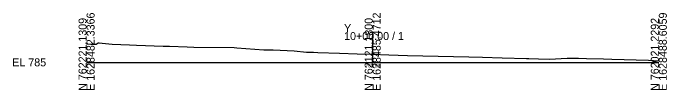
# Model space of a CAD drawing. Extents: x -26 to 203, y -10 to 4017.
# Drawn here: x -25.7 to 202.8, y -9.7 to 17.3 of the extents above; entities that cross this region are included whole.
import ezdxf

# ---------------------------------------------------------------- set-up
doc = ezdxf.new("R2010")
doc.units = 0
for name, color, linetype in [('Default', 7, 'Continuous'), ('Exist Cross Section Cell', 7, 'Continuous'), ('Exist XS Center Line Elevation Label', 7, 'Continuous'), ('Exist XS Ground Line', 7, 'Continuous')]:
    doc.layers.add(name, color=color, linetype=linetype)

msp = doc.modelspace()

# ---------------------------------------------------------------- linework, layer by layer
at = {"layer": 'Exist Cross Section Cell'}
for p, q in [((100, 0), (100, 10.64)), ((0, 0), (100, 0)), ((100, 0), (200, 0))]:
    msp.add_line(p, q, dxfattribs=at)
at = {"layer": 'Exist XS Ground Line'}
msp.add_lwpolyline([(0, 6.52), (1.54, 6.44), (2.84, 6.39), (3.34, 6.37), (4.04, 6.84), (4.35, 6.83), (5.41, 6.76), (8.91, 6.43), (14.99, 6.19), (17.48, 6.09), (26.79, 5.71), (28.97, 5.74), (35.14, 5.41), (37.52, 5.39), (51.57, 5.21), (52.53, 5.14), (61.93, 4.45), (65.22, 4.36), (72.6, 4.09), (76.91, 3.6), (77.76, 3.54), (79.34, 3.57), (80.79, 3.42), (88.36, 3.19), (94.59, 3), (99.75, 2.84), (105.59, 2.61), (112.15, 2.42), (133.56, 1.99), (138.39, 1.83), (145.29, 1.59), (153.77, 1.34), (154.52, 1.32), (158, 1.26), (161.81, 1.17), (167.93, 1.53), (168.51, 1.53), (169.81, 1.5), (171.99, 1.46), (174.74, 1.41), (180.72, 1.26), (183.53, 1.17), (196.43, 0.78), (200, 0.59)], dxfattribs=at)

# ---------------------------------------------------------------- texts
at = {"layer": 'Default'}
msp.add_text('-', height=0.0001, dxfattribs=at).set_placement((0, 0))
at = {"layer": 'Exist Cross Section Cell'}
for s, p in [('E 1628482.3366', (2.8, -10)), ('E 1628485.4712', (102.8, -10)), ('E 1628488.6059', (202.8, -10)), ('N 762221.1309', (0, -10)), ('N 762121.1800', (100, -10)), ('N 762021.2292', (200, -10))]:
    msp.add_text(s, height=2.8, rotation=90, dxfattribs=at).set_placement(p)
for s, p in [('Y', (90, 10.64)), ('10+00.00 / 1', (90, 7.84)), ('EL 785', (-26, -1.4))]:
    msp.add_text(s, height=2.8, dxfattribs=at).set_placement(p)
at = {"layer": 'Exist XS Center Line Elevation Label'}
msp.add_text('787.83', height=1.2, dxfattribs=at).set_placement((97.46, -1.77))

doc.saveas('drawing.dxf')
